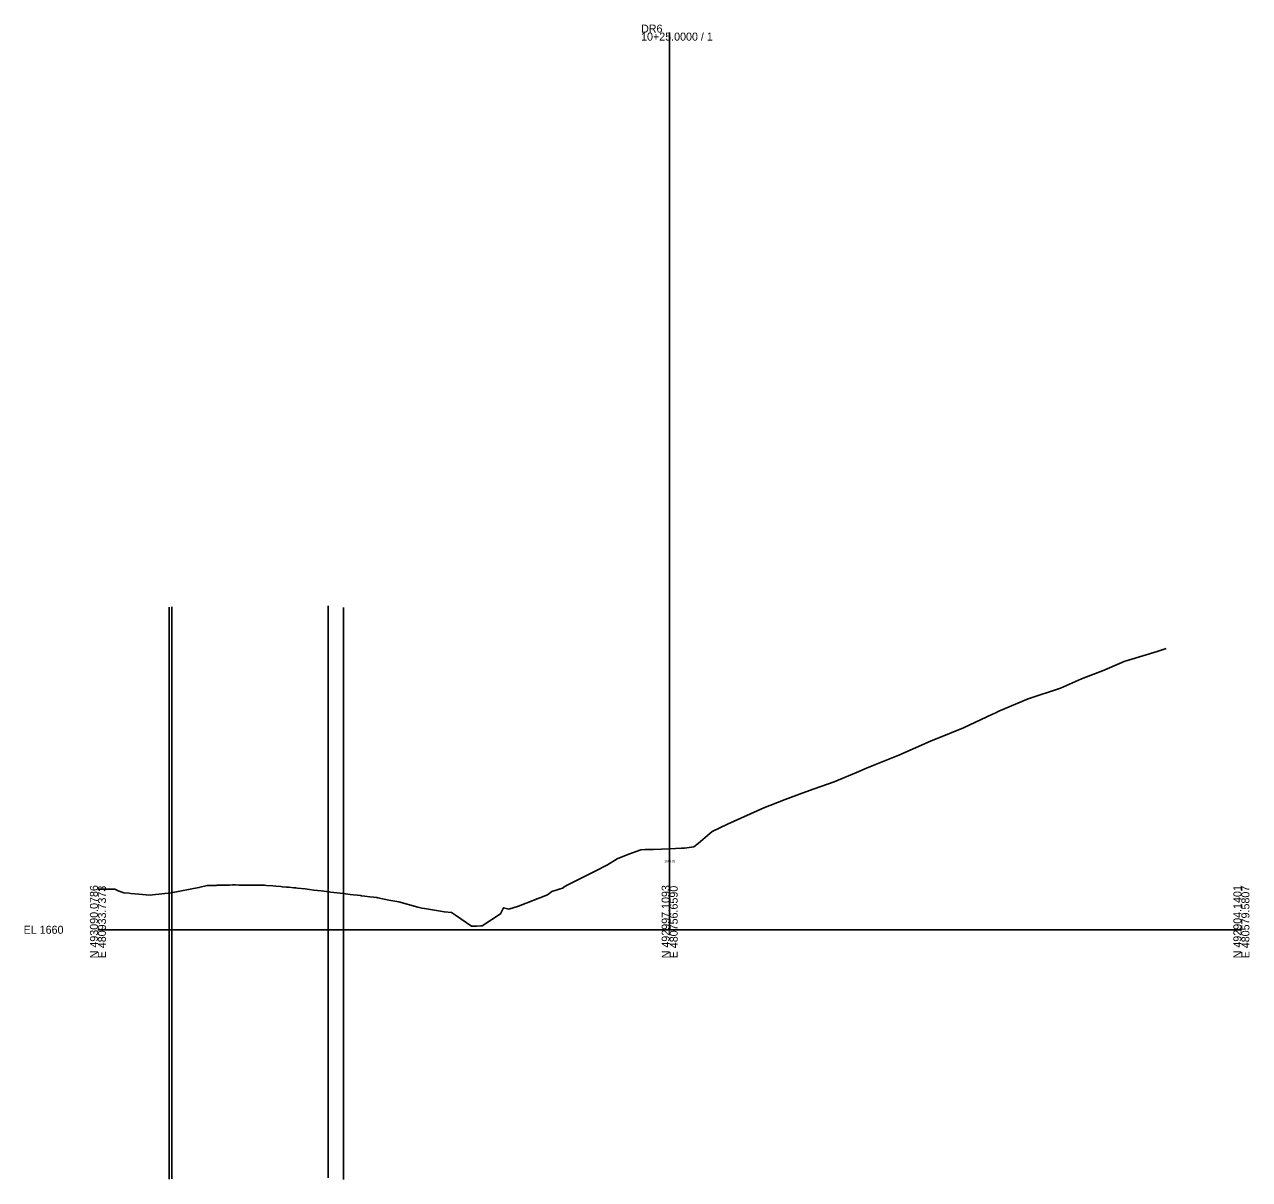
# Model space of a CAD drawing. Extents: x -26 to 403, y -88 to 5647.
# Drawn here: x -25.7 to 402.8, y 412.7 to 816.6 of the extents above; entities that cross this region are included whole.
import ezdxf

# ---------------------------------------------------------------- set-up
doc = ezdxf.new("R2010")
doc.units = 0
for name, color, linetype in [('Exist Cross Section Cell', 7, 'Continuous'), ('Exist XS Center Line Elevation Label', 7, 'Continuous'), ('Exist XS Ground Line', 7, 'Continuous'), ('Scratch_Level_7', 7, 'Continuous')]:
    doc.layers.add(name, color=color, linetype=linetype)

msp = doc.modelspace()

# ---------------------------------------------------------------- linework, layer by layer
at = {"layer": 'Exist Cross Section Cell'}
for p, q in [((200, 500), (200, 813.77)), ((0, 500), (200, 500)), ((200, 500), (400, 500))]:
    msp.add_line(p, q, dxfattribs=at)
at = {"layer": 'Exist XS Ground Line'}
msp.add_lwpolyline([(0, 514.21), (5.86, 514.14), (7.04, 513.66), (9.08, 512.94), (10.94, 512.77), (11.36, 512.72), (14.25, 512.45), (16.83, 512.24), (18.26, 512.11), (19.11, 512.22), (25.63, 512.87), (35.31, 514.73), (38.16, 515.46), (38.76, 515.47), (40.62, 515.51), (41.35, 515.53), (41.7, 515.54), (42.3, 515.56), (44.26, 515.59), (45.97, 515.63), (47.09, 515.66), (48.16, 515.66), (49.3, 515.65), (49.91, 515.65), (51.16, 515.65), (52.7, 515.65), (53.57, 515.65), (55.57, 515.65), (57.2, 515.64), (58.25, 515.58), (58.98, 515.53), (61.18, 515.35), (62.27, 515.26), (63.99, 515.1), (64.39, 515.06), (65.98, 514.92), (66.81, 514.84), (68.47, 514.69), (69.24, 514.62), (69.77, 514.57), (72.44, 514.28), (75.49, 513.9), (78.12, 513.58), (80.89, 513.25), (81.32, 513.2), (83.71, 512.92), (85.8, 512.66), (86.56, 512.57), (88.22, 512.37), (89.42, 512.22), (90.81, 512.06), (91.79, 511.95), (92.21, 511.9), (93.34, 511.76), (95.07, 511.56), (96.35, 511.39), (97.59, 511.23), (97.89, 511.19), (100.17, 510.72), (101.75, 510.4), (105.22, 509.75), (111.93, 507.89), (113.29, 507.56), (114.29, 507.39), (121.2, 506.22), (123.72, 506.05), (125.12, 505.09), (130.73, 501.28), (131.24, 501.29), (132.47, 501.29), (134, 501.34), (134.39, 501.33), (140.83, 505.56), (141.93, 507.71), (143.78, 507.15), (147.17, 508.29), (157.25, 512.18), (158.78, 513.33), (162.82, 514.7), (162.88, 514.86), (164.87, 515.97), (173.69, 520.41), (178.26, 522.74), (181.62, 524.86), (185.42, 526.3), (189.93, 527.98), (191.43, 528.03), (194.4, 528.12), (200, 528.35), (204.16, 528.53), (205.23, 528.55), (206.06, 528.67), (208.4, 529), (210, 530.17), (214.88, 534.4), (220.29, 536.98), (232.95, 542.62), (235.01, 543.41), (240.36, 545.52), (246.31, 547.82), (250.55, 549.25), (257.6, 551.76), (265.4, 555.04), (268.9, 556.51), (272.06, 557.8), (280.2, 561.05), (289.18, 565.06), (291.49, 566.09), (293.58, 566.92), (302.79, 570.57), (312.97, 575.4), (314.09, 575.91), (314.43, 576.07), (315.1, 576.41), (325.38, 580.79), (336.68, 584.52), (344.06, 587.77), (347.98, 589.29), (351.47, 590.58), (358.13, 593.44), (359.27, 593.88), (360.53, 594.28), (370.57, 597.29), (373.69, 598.35)], dxfattribs=at)
at = {"layer": 'Scratch_Level_7'}
for p, q in [((25.89, 612.92), (25.89, 412.92)), ((80.53, 613.29), (80.53, 413.29)), ((24.93, 612.8), (24.93, 412.8)), ((85.87, 612.65), (85.87, 412.65))]:
    msp.add_line(p, q, dxfattribs=at)

# ---------------------------------------------------------------- texts
at = {"layer": 'Exist Cross Section Cell'}
for s, p in [('DR6', (190, 813.77)), ('10+25.0000 / 1', (190, 810.97)), ('EL 1660', (-26, 498.6))]:
    msp.add_text(s, height=2.8, dxfattribs=at).set_placement(p)
for s, p in [('N 493090.0786', (0, 490)), ('E 480933.7373', (2.8, 490)), ('N 492997.1093', (200, 490)), ('E 480756.6590', (202.8, 490)), ('N 492904.1401', (400, 490)), ('E 480579.5807', (402.8, 490))]:
    msp.add_text(s, height=2.8, rotation=90, dxfattribs=at).set_placement(p)
at = {"layer": 'Exist XS Center Line Elevation Label'}
msp.add_text('1688.35', height=0.75, dxfattribs=at).set_placement((198.21, 523.6))

doc.saveas('drawing.dxf')
